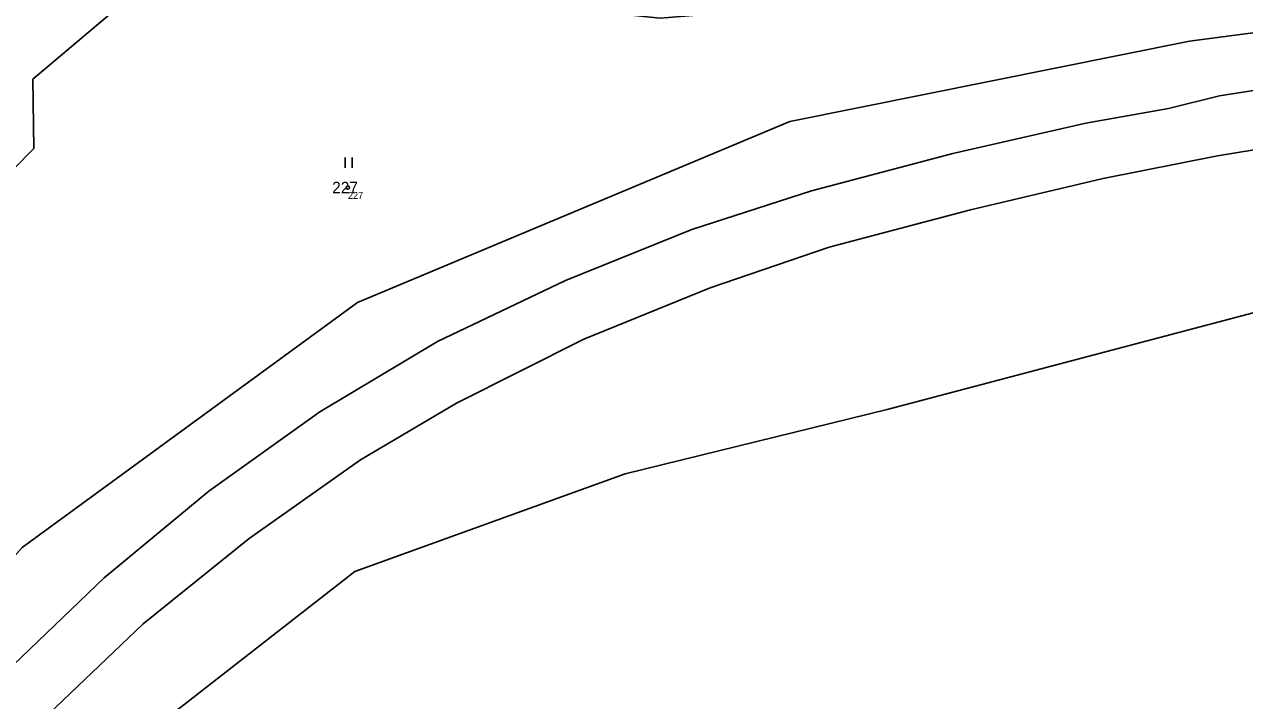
# Model space of a CAD drawing. Extents: x -554500 to -548272, y -1079733 to -1073730.
# Drawn here: x -552182.3 to -552002.8, y -1076624.7 to -1076525.1 of the extents above; entities that cross this region are included whole.
import ezdxf

# ---------------------------------------------------------------- set-up
doc = ezdxf.new("R2010")
doc.units = 0
for name, color, linetype in [('Definiční body', 7, 'Continuous'), ('Hranice parcel', 7, 'Continuous'), ('Parcelní čísla', 7, 'Continuous'), ('Polygon parcely', 7, 'Continuous'), ('Vnitřní kresba', 7, 'Continuous'), ('Značky kultur', 7, 'Continuous')]:
    doc.layers.add(name, color=color, linetype=linetype)

msp = doc.modelspace()

# ---------------------------------------------------------------- linework, layer by layer
at = {"layer": 'Definiční body'}
msp.add_circle((-552134.73, -1076549.16994), 0.25, dxfattribs=at)
at = {"layer": 'Hranice parcel'}
for points in [[(-552154.52, -1076510.74), (-552181.08, -1076533.2), (-552180.97, -1076543.39), (-552186.9, -1076549.41)], [(-552190.26, -1076610.7), (-552182.66, -1076602.14), (-552133.32, -1076566.09), (-552069.7, -1076539.42), (-552010.87, -1076527.63), (-551999.3, -1076526.07)], [(-551741.79, -1076544.44), (-551804.47, -1076535.5), (-551863.78, -1076542.51), (-551921.68, -1076552.63), (-551987.57, -1076563.95), (-552055.38, -1076581.85), (-552093.92, -1076591.29), (-552133.7, -1076605.67), (-552177.37, -1076639.74), (-552180.28, -1076643.36)]]:
    msp.add_lwpolyline(points, dxfattribs=at)
at = {"layer": 'Polygon parcely'}
for points in [[(-552180.97, -1076543.39), (-552186.9, -1076549.41), (-552184.28, -1076554.84), (-552184.28, -1076561.1), (-552196.79, -1076592.18), (-552196.51, -1076597.03), (-552190.26, -1076610.7), (-552182.66, -1076602.14), (-552133.32, -1076566.09), (-552069.7, -1076539.42), (-552010.87, -1076527.63), (-551999.3, -1076526.07), (-552001.37, -1076522.97), (-552043.68, -1076520.48), (-552088.8, -1076524.21), (-552101.18, -1076522.96), (-552154.52, -1076510.74), (-552181.08, -1076533.2)], [(-552154.52, -1076510.74), (-552186.31, -1076524.73), (-552196.07, -1076529.9), (-552196.55, -1076533.59), (-552189.35, -1076544.34), (-552186.9, -1076549.41), (-552180.97, -1076543.39), (-552181.08, -1076533.2)]]:
    msp.add_lwpolyline(points, close=True, dxfattribs=at)
for points in [[(-551999.3, -1076526.07), (-552010.87, -1076527.63), (-552069.7, -1076539.42), (-552133.32, -1076566.09), (-552182.66, -1076602.14), (-552190.26, -1076610.7), (-552192.81, -1076613.57), (-552196.25, -1076617.44), (-552232.91, -1076658.76), (-552278.63, -1076708.6), (-552281.34, -1076714.84), (-552283.97, -1076720.95), (-552309.19, -1076755.85), (-552313.73, -1076761.03), (-552315.85, -1076763.45), (-552328.64, -1076778.02), (-552330.5, -1076780.14), (-552346.57, -1076799.53), (-552374.22, -1076832.9), (-552399.11, -1076854.21), (-552447.65, -1076889.79), (-552512.89, -1076927.79), (-552539.21, -1076938.07), (-552603.07, -1076955.53)], [(-552321.39, -1076821.89), (-552310.33, -1076805.85), (-552308.58, -1076803.31), (-552284.98, -1076768.63), (-552268.97, -1076744.95), (-552264, -1076740.5), (-552261.86, -1076738.59), (-552248.14, -1076726.32), (-552219.76, -1076692.55), (-552185.17, -1076649.46), (-552180.28, -1076643.36), (-552177.37, -1076639.74), (-552133.7, -1076605.67), (-552093.92, -1076591.29), (-552055.38, -1076581.85), (-551987.57, -1076563.95)], [(-551987.57, -1076563.95), (-552055.38, -1076581.85), (-552093.92, -1076591.29), (-552133.7, -1076605.67), (-552177.37, -1076639.74), (-552180.28, -1076643.36), (-552117.46, -1076756.01), (-552095.79, -1076793), (-552037.18, -1076849.51), (-551952.84, -1076911.7)]]:
    msp.add_lwpolyline(points, dxfattribs=at)
at = {"layer": 'Vnitřní kresba'}
for p, q in [((-551976.66, -1076530.93), (-552006.45, -1076535.68)), ((-552006.45, -1076535.68), (-552013.98, -1076537.5)), ((-552026.15, -1076539.67), (-552013.98, -1076537.5)), ((-552006.75, -1076544.47), (-551975.35, -1076539.33)), ((-552026.15, -1076539.67), (-552045.7, -1076544.17)), ((-552045.7, -1076544.17), (-552066.52, -1076549.63)), ((-552023.61, -1076547.84), (-552006.75, -1076544.47)), ((-552043.12, -1076552.45), (-552023.61, -1076547.84)), ((-552066.52, -1076549.63), (-552084.12, -1076555.33)), ((-552063.93, -1076557.94), (-552043.12, -1076552.45)), ((-552084.12, -1076555.33), (-552102.72, -1076562.86)), ((-552081.43, -1076563.95), (-552063.93, -1076557.94)), ((-552102.72, -1076562.86), (-552121.57, -1076571.82)), ((-552100.04, -1076571.47), (-552081.43, -1076563.95)), ((-552138.86, -1076582.2), (-552121.57, -1076571.82)), ((-552118.74, -1076580.89), (-552100.04, -1076571.47)), ((-552118.74, -1076580.89), (-552132.87, -1076589.25)), ((-552155.2, -1076593.85), (-552138.86, -1076582.2)), ((-552132.87, -1076589.25), (-552149.28, -1076600.82)), ((-552170.58, -1076606.64), (-552155.2, -1076593.85)), ((-552149.28, -1076600.82), (-552164.85, -1076613.38)), ((-552191.62, -1076626.74), (-552170.58, -1076606.64)), ((-552164.85, -1076613.38), (-552184.79, -1076632.41))]:
    msp.add_line(p, q, dxfattribs=at)
at = {"layer": 'Značky kultur'}
for p, q in [((-552135.121, -1076546.24), (-552135.121, -1076544.74)), ((-552134.12, -1076546.24), (-552134.12, -1076544.74))]:
    msp.add_line(p, q, dxfattribs=at)

# ---------------------------------------------------------------- texts
at = {"layer": 'Definiční body'}
msp.add_text('227', height=0.999996, dxfattribs=at).set_placement((-552134.73, -1076550.826))
at = {"layer": 'Parcelní čísla'}
msp.add_text('227', height=1.699998, dxfattribs=at).set_placement((-552137.055, -1076550.02))

doc.saveas('drawing.dxf')
